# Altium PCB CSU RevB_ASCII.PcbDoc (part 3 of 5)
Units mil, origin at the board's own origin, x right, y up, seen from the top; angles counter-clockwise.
Board outline 5905.51 x 4330.71 mil, 8 copper layers (Top Layer, InternalPlane1, MidLayer1, InternalPlane2, MidLayer2, InternalPlane3, MidLayer3, Bottom Layer); 265 components, 387 nets, 1910 pads, 1151 vias.
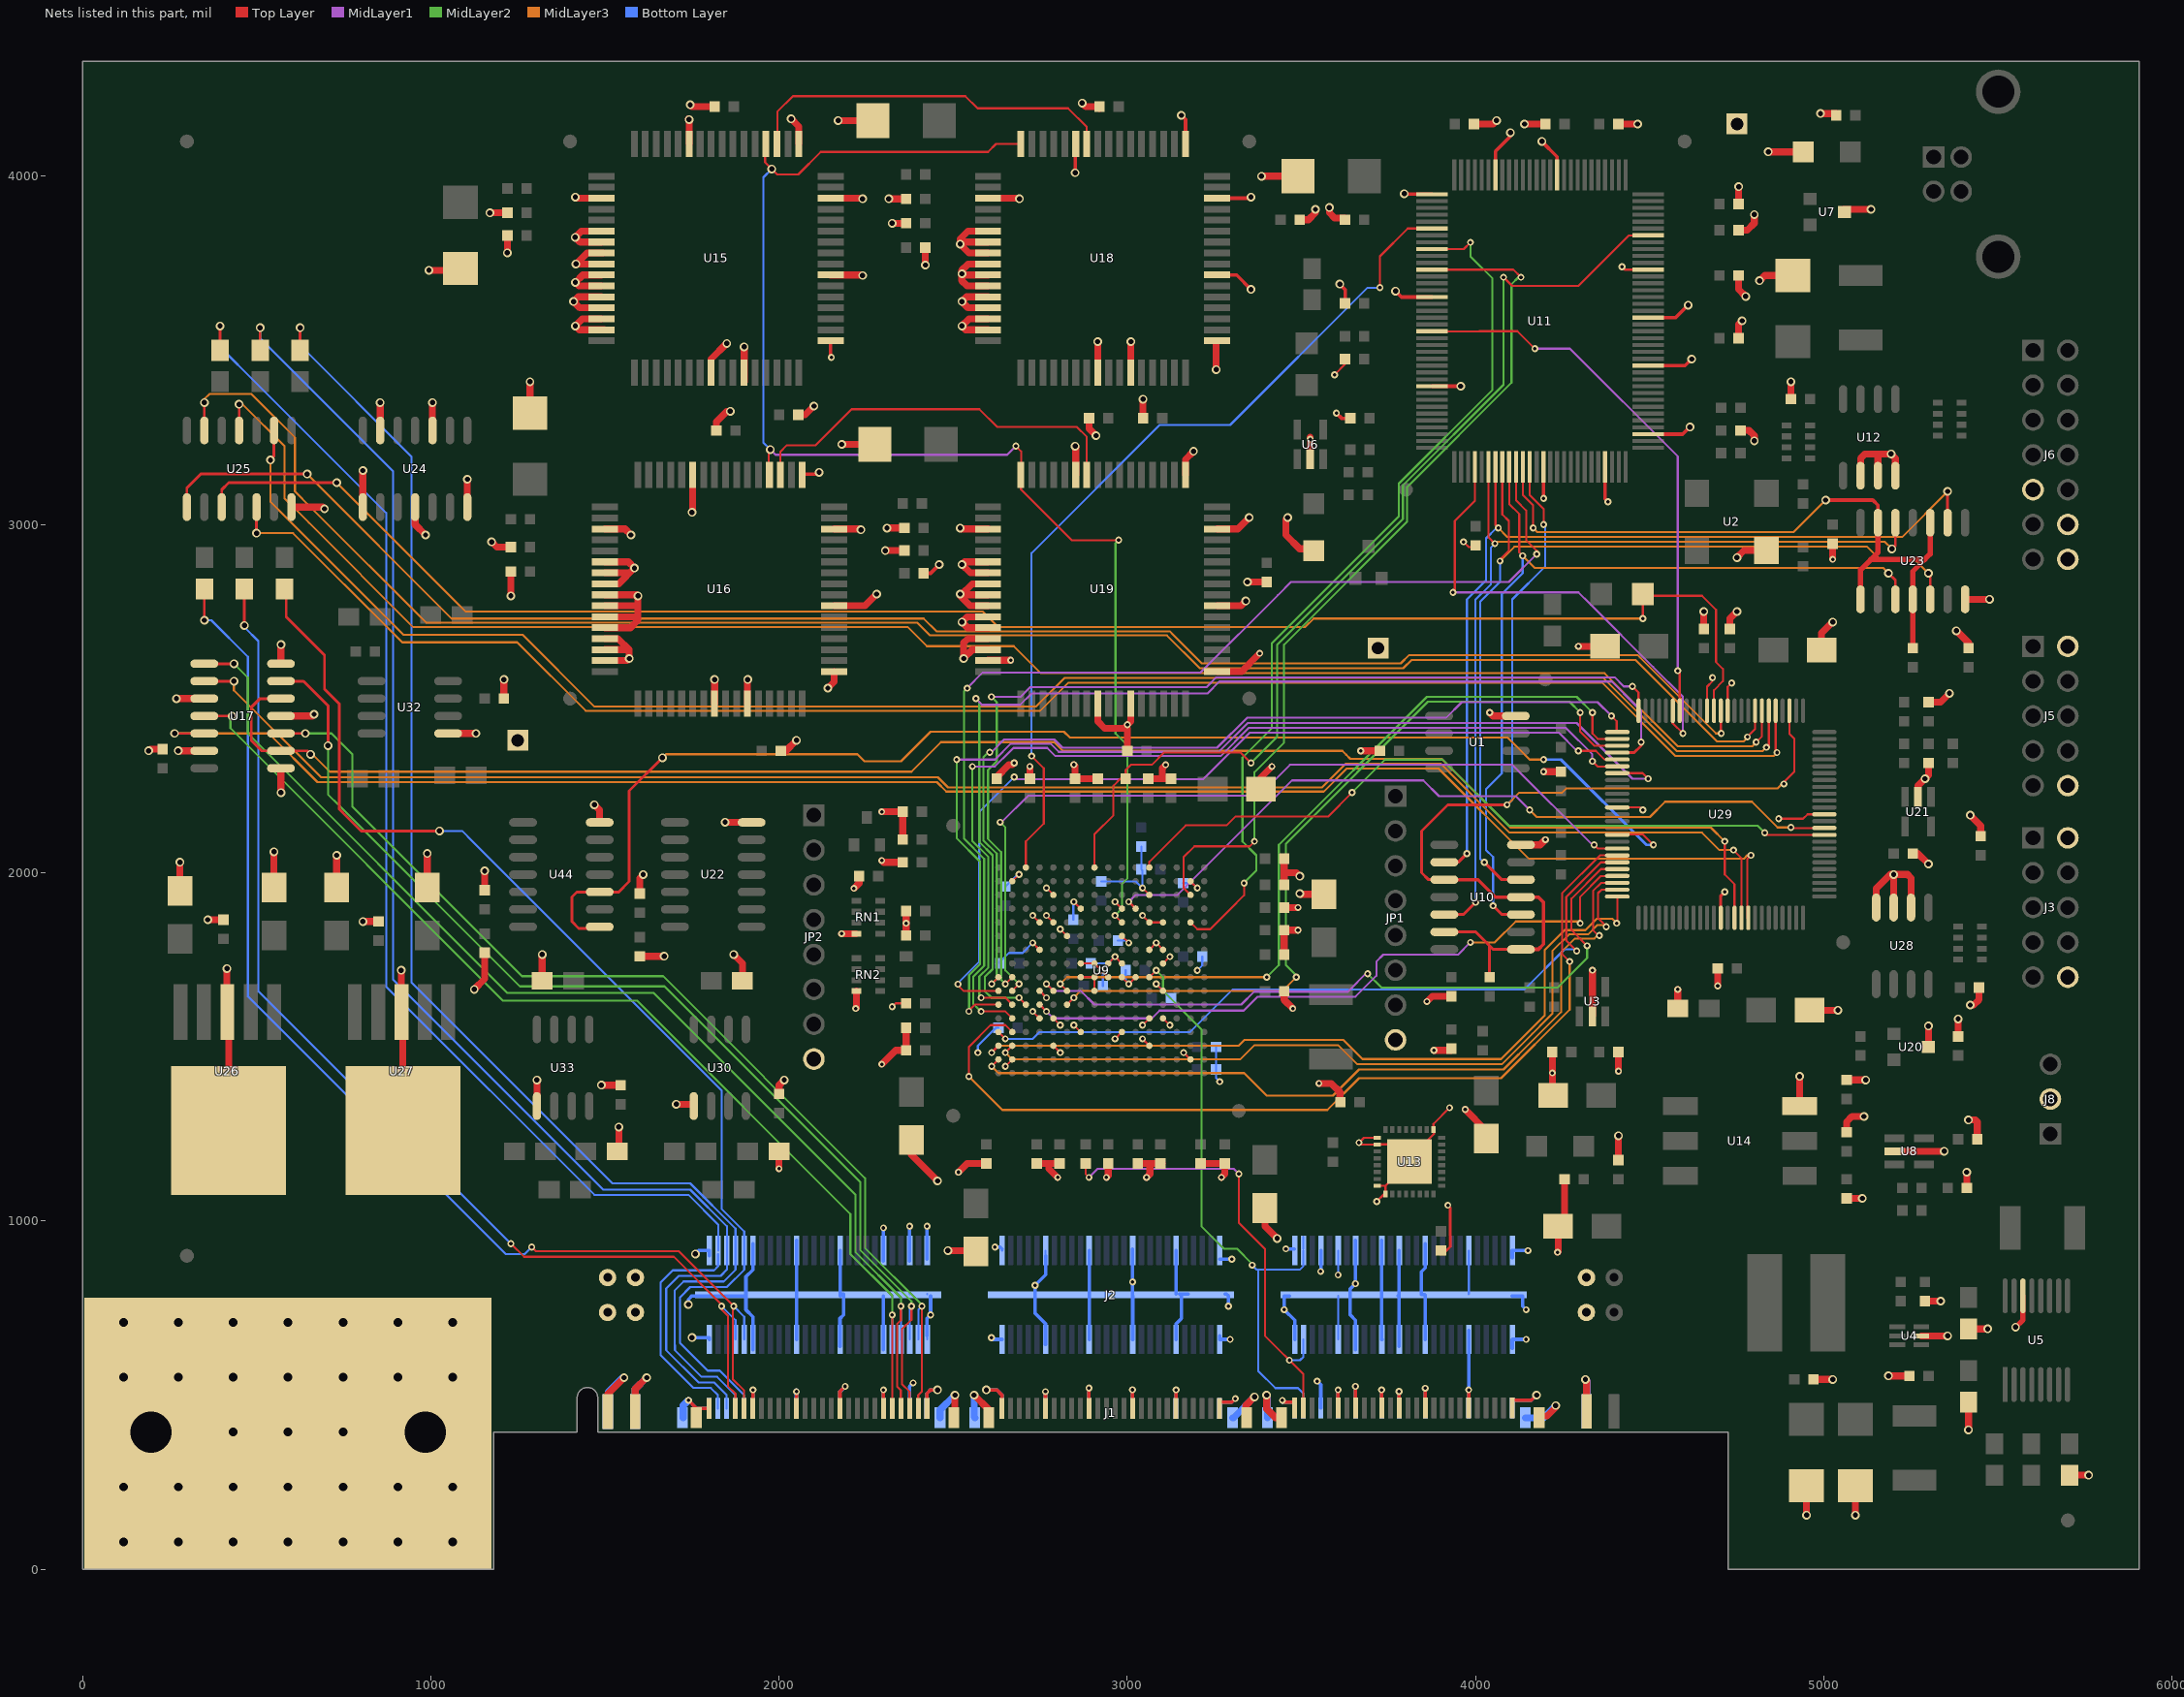
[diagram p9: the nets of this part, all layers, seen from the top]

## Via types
v1: diameter 20, hole 10, Top Layer to Bottom Layer, 647 vias
v2: diameter 25, hole 15, Top Layer to Bottom Layer, 352 vias
v3: diameter 20, hole 10, Top Layer to Bottom Layer, tented top, 151 vias
v4: diameter 20, hole 10, Top Layer to Bottom Layer, tented bottom, 1 vias

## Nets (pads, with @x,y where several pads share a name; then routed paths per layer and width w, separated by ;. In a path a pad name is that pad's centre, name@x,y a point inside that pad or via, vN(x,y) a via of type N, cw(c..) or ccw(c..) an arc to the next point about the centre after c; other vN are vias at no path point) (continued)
FIFO_TRANS_CLK: U9.E10 U15.52 U16.52 U18.64 U19.64 | length 4069.9
  Top Layer w6: U15.52@1962.44,4093 1960,4090.56 1960,4040 1995,4005 2055,4005 2120,4070 2600,4070 2623,4093 U18.64@2694.49,4093 ; U16.52@1972.44,3143 1970,3145.44 1970,3205 1975,3210 v2(1975,3215) ; v1(2680,3225) 2695,3210 2695,3143.51 U19.64@2694.49,3143 2694.49,3100.51 2840,2955 v1(2975,2955) ; v3(2964.65,1877.2) U9.E10@2984.33,1857.52
  MidLayer1 w6: v2(1975,3215) 1990,3200 2655,3200 v1(2680,3225)
  MidLayer2 w6: v3(2964.65,1877.2) 2984.33,1896.89 2984.33,1967.63 2999.7,1983 2999.7,2366.33 2966,2400.03 2966,2946 v1(2975,2955)
  Bottom Layer w6: v2(1975,3215) 1955,3235 1955,3996.98 v2(1979.01,4020.99)
FIRST_BYTE: U11.85 U29.19 | length 1587.4
  Top Layer w6: U11.85@3874.45,3554.65 4010,3554.65 ; 4010,3555 4120,3555 v1(4170,3505) ; v1(4580,2580) 4585.67,2574.33 U29.19@4585.67,2465
  MidLayer1 w6: v1(4170,3505) 4270.6,3505 4580,3195.6 v1(4580,2580)
FLAG_B: U9.A3 U11.70 | length 2542.4
  Top Layer w6: U9.A3@2708.74,2015 2708.74,2090 2760,2141.26 2760,2300 v1(2725,2335) ; v1(3725,3680) 3725,3770 3804.92,3849.92 U11.70@3890,3849.92
  Bottom Layer w6: v1(2725,2335) 2725,2917.91 3092.6,3285.51 3295,3285.51 3689.49,3680 v1(3725,3680)
FP_SEL_0_N: U9.D11 U29.86 | length 2259.9
  Top Layer w6: v3(3004.02,1916.57) U9.D11@3023.7,1896.89 ; v1@4906.61,2128.39 U29.86@5001.02,2128.39
  MidLayer1 w6: v3(3004.02,1916.57) 3023.7,1936.26 3144.14,1936.26 3472.88,2265 3850,2265 3895,2220 4115,2220 v1(4155,2180)
  MidLayer3 w6: v1(4155,2180) 4175,2160 4500,2160 4544,2204 4792.97,2204 4866.97,2130 v1(4905,2130)
FP_SEL_1_N: U9.A12 U29.85 | length 2165.6
  Top Layer w6: U9.A12@3063.07,2015 3063.07,2031.43 3167.64,2136 3284.94,2136 3309.94,2161 3576,2161 v1(3645,2230) ; v1(4830,2115) 4836.3,2108.7 U29.85@5001.02,2108.7
  MidLayer2 w6: v1(3645,2230) 3740,2325 3905,2325 4095,2135 4810,2135 v1(4830,2115)
FPGA_RESET_N: U9.M2 U11.112 | length 3145.1
  Top Layer w6: v1(2580,1601.61) 2649.68,1601.61 U9.M2@2669.37,1581.93 ; U11.112@4115.83,3165.63 4115.83,3069.17 4145,3040 4145,2955 4175,2925 v1(4175,2915)
  MidLayer1 w6: v1(2540,2530) 2585,2575 3210,2575 3431.86,2796.86 3470,2835 4095,2835 v1(4175,2915)
  MidLayer2 w6: v1(2540,2530) 2531.57,2521.57 2531.57,2097.45 2589,2040.03 2589,1732.94 2557.63,1701.57 2557.63,1623.99 v1(2580,1601.61)
FPGA_SEL_N: R21.1 U10.1 U10.4 U10.10 U10.13 U11.114 U29.3 | length 3372.7
  Top Layer w6: U11.114@4155.2,3165.63 4155.2,3085 4195,3045.2 v1(4195,3000) ; v1@4882.5,2257.5 4915,2290 4915,2384.8 4900.63,2399.17 U29.3@4900.63,2465
  Top Layer w8: U10.10@3900,1980 3865,1980 3845,2000 3845,2120 3920,2195 v1(4090,2195) ; U10.13@3910,1830 4000,1830 4050,1780 U10.1@4135,1780 ; R21.1@4039.99,1700 4039.99,1790.01
  Top Layer w10: U10.10@3900,1980 4007.14,1980 4057.14,1930 4180,1930 4195,1915 4195,1795 4180,1780 U10.1@4135,1780
  MidLayer3 w6: v1(4090,2195) 4125,2230 4248.03,2230 4260.03,2242 4867,2242 v1@4880,2255
  Bottom Layer w6: v1(4090,2195) 4105,2210 4105,2785 4200,2880 v1@4200,2995
  other v1: 4885,2255
FRAME_START: U9.E15 U11.73 | length 2562.9
  Top Layer w6: U9.E15@3181.18,1857.52 3200.87,1837.83 3237.83,1837.83 3292.93,1892.93 3335,1935 v1(3335,1970) ; U11.73@3865,3790 U11.73@3875,3790 ; U11.73@3874.45,3790.87 3965.87,3790.87 v1(3985,3810)
  MidLayer2 w6: v1(3335,1970) 3340,1970 3340,1976.4 3370,2006.4 3370,2050 3330.55,2089.45 3330.55,2330.55 3415,2415 3415,2659.4 3779.2,3023.6 3779.2,3117.23 4048.14,3386.17 4048.14,3706.86 3985,3770 v1(3985,3810)
GAIN_4X: J1.50 J2.50 U9.J12 | length 1735
  Top Layer w6: U9.J12@3063.07,1700.04 v3(3082.76,1719.72)
  MidLayer2 w6: v3(3082.76,1719.72) 3102.44,1700.04 3102.44,1660.67 3212.69,1550.42 3212.69,984.95 3264.02,933.62 3277.64,920 3315,920 3358.35,876.65 v1(3358.35,873.27)
  Bottom Layer w6: v1(3358.35,873.27) 3371.61,860 3495,860 3505.51,870.51 J2.50@3505.51,914.96 ; 3376,860 3376,569 3425.01,519.99 3490.01,519.99 3505,505 3505,463.05 J1.50@3505.21,462.85 ; J2.50@3505.51,920 J2.50@3505.51,954.49
GND: C1.2 C2.2 C3.1 C4.2 C5.1 C7.2 C8.1 C9.2 C10.2 C11.2 C12.2 C13.2 C14.2 C15.1 C16.2 C18.1 C19.2 C20.1 C21.2 C22.1 C23.2 C24.2 C25.1 C26.1 C27.1 C28.1 C29.2 C30.1 C31.2 C32.2 C33.1 C34.2 C35.1 C36.1 C37.1 C38.2 C39.2 C40.2 C41.2 C42.1 C43.1 C44.1 C45.1 C46.2 C47.1 C48.1 C49.2 C50.1 C51.1 C52.1 C53.1 C54.2 C55.2 C56.2 C57.1 C58.1 C59.1 C60.1 C61.1 C62.1 C63.1 C64.1 C65.1 C66.1 C67.1 C68.2 C69.2 C70.2 C71.2 C72.2 C73.1 C74.2 C75.1 C76.1 C77.2 C78.2 C79.2 C80.2 C81.2 C82.2 C83.2 C84.2 C85.2 C86.2 C87.2 C88.2 C89.2 C90.2 C91.2 C92.2 C93.2 C94.2 C95.2 C96.2 C97.2 C98.2 C99.2 C100.1 C101.2 C102.2 C103.2 C104.2 C105.1 C106.1 C107.2 C108.2 C109.2 C110.2 C111.2 C112.2 C113.1 C114.1 C115.1 C116.1 C117.1 C118.1 C119.1 C120.1 C121.1 C122.1 C123.1 C124.1 C125.1 C126.2 C127.2 C128.1 C129.1 C130.1 C131.1 C132.1 C133.1 C134.1 C135.1 C136.2 C137.2 C138.2 C140.1 C142.2 J1.1 J1.2 J1.11 J1.12 J1.21 J1.22 J1.27 J1.28 J1.31 J1.32 J1.37 J1.38 J1.41 J1.42 J1.46 J1.51 J1.52 J1.53 J1.54 J1.63 J1.64 J1.73 J1.74 J1.83 J1.84 J1.93 J1.94 J1.103 J1.104 J1.105 J1.106 J1.110 J1.115 J1.116 J1.125 J1.126 J1.135 J1.136 J1.145 J1.146 J1.155 J1.156 J1.157 J1.158 J1.159 J1.160 J1.161 J1.162 J1.163 J1.PC03 J1.PC04 J1.PC05 J1.PC06 J1.PC07 J1.PC08 J2.1 J2.2 J2.11 J2.12 J2.21 J2.22 J2.27 J2.28 J2.31 J2.32 J2.37 J2.38 J2.41 J2.42 J2.46 J2.51 J2.52 J2.53 J2.54 J2.63 J2.64 J2.73 J2.74 J2.83 J2.84 J2.93 J2.94 J2.103 J2.104 J2.105 J2.106 J2.110 J2.115 J2.116 J2.125 J2.126 J2.135 J2.136 J2.145 J2.146 J2.155 J2.156 J2.157 J2.158 J2.159 J2.PC03 J2.PC04 J2.PC05 J2.PC06 J2.PC07 J2.PC08 J3.2 J3.10 J5.2 J5.10 J6.9 J6.12 J6.14 J8.2 JP1.8 JP2.8 L2.2 pad.0 pad.1 pad.2 pad.3 pad.4 pad.5 R8.1 R9.1 R14.1 R15.1 R17.2 R20.1 R24.1 R39.1 R42.1 R48.1 R49.1 R51.2 R54.2 RN1.8 RN2.8 TP1.1 TP2.1 TP3.1 U1.4 U2.2 U3.2 U4.5 U5.14 U6.2 U7.3 U8.2 U9.B2 U9.B15 U9.C5 U9.C12 U9.D7 U9.D10 U9.E4 U9.E5 U9.E12 U9.E13 U9.F6 U9.F10 U9.G4 U9.G12 U9.G13 U9.H7 U9.H8 U9.H9 U9.H10 U9.H13 U9.J7 U9.J8 U9.J9 U9.J10 U9.J11 U9.K4 U9.K8 U9.K13 U9.M4 U9.M5 U9.M12 U9.M13 U9.N7 U9.N10 U9.P5 U9.P12 U9.R2 U9.R15 U10.7 U11.3 U11.13 U11.20 U11.27 U11.49 U11.58 U11.65 U11.80 U11.93 U11.116 U11.125 U12.2 U12.3 U12.4 U13.1 U13.2 U13.8 U13.9 U13.25 U13.T_PAD U14.3 U15.3 U15.6 U15.7 U15.8 U15.9 U15.10 U15.11 U15.12 U15.13 U15.14 U15.15 U15.24 U15.27 U15.33 U15.39 U15.46 U15.49 U15.59 U16.3 U16.6 U16.7 U16.8 U16.9 U16.10 U16.11 U16.12 U16.13 U16.14 U16.15 U16.24 U16.27 U16.33 U16.39 U16.46 U16.49 U16.59 U17.1 U17.4 U17.7 U17.10 U17.13 U18.3 U18.6 U18.7 U18.8 U18.9 U18.10 U18.11 U18.12 U18.13 U18.14 U18.15 U18.24 U18.27 U18.33 U18.39 U18.46 U18.49 U18.59 U19.3 U19.6 U19.7 U19.8 U19.9 U19.10 U19.11 U19.12 U19.13 U19.14 U19.15 U19.24 U19.27 U19.33 U19.39 U19.46 U19.49 U19.59 U20.3 U21.2 U22.7 U23.7 U24.1 U24.4 U24.7 U24.10 U24.13 U25.7 U26. U26.3 U27. U27.3 U28.2 U28.3 U28.4 U29.12 U29.15 U29.37 U29.63 U29.88 U30.5 U32.1 U33.5 U44.7 | length 33840.3
  Top Layer w6: v2(190,2350) v2@195,2355 ; v2(915,1720) v2@916,1719 ; v1@1924.71,514.71 v1(1925,515) ; C47.1@2045,3315.01 C47.1@2055,3315.02 ; v1@2049.71,509.71 v1(2050,510) ; v2@2110,3145 v2(2115,3150) ; v1@2148,3482 v1(2150,3480) ; v1(2220,1610) v1@2222,1612 ; v2@2232.99,2987.01 v2(2235,2985) ; v1@2299.71,514.71 v1(2300,515) ; v1(2325,1615) 2335.01,1625.01 C21.2@2365,1625.01 ; C103.2@2355,2175.01 C103.2@2365,2165.01 ; v2@2520,2795 v2@2523.03,2798.03 ; v2(2520,2990) v2@2522.99,2987.01 ; v3(2649.68,1444.13) U9.R2@2669.37,1463.82 ; U9.B2@2669.37,1975.63 v3(2689.06,1995.32) ; C83.2@2720.01,2260 C83.2@2720.01,2270 ; v3(2728.43,1601.61) U9.M4@2748.11,1581.93 ; v3(2728.43,1798.46) U9.G4@2748.11,1778.78 ; v3(2728.43,1877.2) U9.E4@2748.11,1857.52 ; C96.2@2734.99,1165 C96.2@2739.99,1165 ; U9.K4@2748.11,1660.67 v3(2767.8,1640.98) ; v1@2764.86,509.86 v1(2765,510) ; v3(2767.8,1877.2) U9.E5@2787.48,1857.52 ; v3(2767.8,1955.94) U9.C5@2787.48,1936.26 ; U9.P5@2787.48,1503.19 v3(2807.17,1483.5) ; U9.M5@2787.48,1581.93 v3(2807.17,1562.24) ; v3(2807.17,1837.83) U9.F6@2826.85,1818.15 ; v3(2846.54,1562.24) U9.N7@2866.22,1542.56 ; v3(2846.54,1916.57) U9.D7@2866.22,1896.89 ; U9.J7@2866.22,1700.04 U9.J8@2905.59,1700.04 ; U9.H7@2866.22,1739.41 U9.H8@2905.59,1739.41 U9.J9@2944.96,1700.04 ; v1(2889.86,519.86) v1@2890,519.73 ; U9.K8@2905.59,1660.67 U9.J8@2905.59,1700.04 ; v3(2925.28,1719.72) U9.J8@2905.59,1700.04 ; U9.H9@2944.96,1739.41 v3(2964.65,1759.09) U9.H10@2984.33,1739.41 ; v3(2964.65,1522.87) U9.N10@2984.33,1542.56 ; v3(2964.65,1916.57) U9.D10@2984.33,1896.89 ; U9.J10@2984.33,1700.04 v3(3004.02,1680.35) U9.J11@3023.7,1700.04 ; U9.F10@2984.33,1818.15 v3(3004.02,1798.46) ; 2990,2415 3000,2415 ; U19.27@3009.45,2485 U19.27@3009.45,2486 ; v3(3043.39,1522.87) U9.P12@3063.07,1503.19 ; v3(3043.39,1562.24) U9.M12@3063.07,1581.93 ; v3(3043.39,1877.2) U9.E12@3063.07,1857.52 U9.E13@3102.44,1857.52 ; v3(3043.39,1955.94) U9.C12@3063.07,1936.26 ; U9.G12@3063.07,1778.78 v3(3082.76,1798.46) U9.G13@3102.44,1778.78 ; v3(3082.76,1680.35) U9.K13@3102.44,1660.67 ; U9.M13@3102.44,1581.93 v3(3122.13,1562.24) ; U9.H13@3102.44,1739.41 v3(3122.13,1759.09) ; v3(3161.5,1483.5) U9.R15@3181.18,1463.82 ; U9.B15@3181.18,1975 v3@3200.87,1955.32 ; C91.2@3200,1165 C91.2@3209.99,1165 ; U19.46@3258,2987.01 U19.46@3265,2987.01 ; J1.53@3264.86,461.79 3264.86,479.86 J1.53@3265,480 ; C136.2@3383,2240 3383,2268 v1@3417.5,2302.5 ; v1(3595,3430) 3625,3460 R8.1@3625,3474.99 ; v1(3605,515) v1@3605.21,514.79 ; v1(3665,1225) 3678.9,1238.9 U13.1@3717.48,1238.9 ; v1@3670.79,1219.21 U13.2@3717.48,1219.21 ; v1@3715,1055 3737.48,1077.48 U13.9@3741.1,1077.48 3741.1,1101.1 ; U13.8@3717.48,1101.1 3741.1,1101.1 ; U13.2@3720,1220 3765,1220 U13.T_PAD@3775,1210 ; v1(3730,515) v1@3730.21,514.79 ; U13.T_PAD@3755,1115 3741.1,1101.1 ; v1(3780.21,510.21) v1@3785,515 ; v2(3795,3950) v2@3796.65,3948.35 ; U13.T_PAD@3855,1225 3880,1250 U13.25@3880,1265 ; U13.25@3878.9,1262.52 3878.9,1278.9 v1(3925,1325) ; v1(3965,2950) 3980,2935 C25.1@4000,2935 ; v1@4194.57,3075.43 v1(4195,3075) ; U29.37@4406.54,2187.44 4472.56,2187.44 v1(4480,2180) ; v1(4420,3740) 4428.19,3731.81 U11.27@4495,3731.81 ; U29.15@4664.41,2465 4664.41,2534.41 4680,2550 ; U29.12@4723.46,2465 4723.46,2533.46 v1(4735,2545) ; v1(4870,2155) 4940,2155 4952.76,2167.76 U29.88@5001.02,2167.76 ; 5152.5,3202.5 5155,3200 ; C10.2@5415,2640.01 C10.2@5415,2650
  Top Layer w8: C33.1@3900.01,915 3916,915 3927,926 3927,1038 v1(3920,1045) ; U29.63@4703.78,1870.51 4703.78,1933.78 v1(4715,1945)
  Top Layer w10: v1(1740,485) 1763.21,461.79 J1.155@1799.71,461.79 ; J1.145@1925,440 v1(1925,515) ; v1@2049.71,509.71 2050,509.41 J1.135@2050,440 ; U16.49@2070,3145 v2@2110,3145 ; v1@2148,3482 U15.33@2148,3527.56 ; J1.125@2175,445 2175,510 v1(2190,525) ; v1@2299.71,514.71 2300,514.41 J1.115@2300,440 ; C51.1@2415,2860.01 2435.01,2860.01 v2(2460,2885) ; J1.105@2424.71,461.79 2425,462.08 2425,505 2435,515 v2(2455,515) ; v2(2595,515) 2625,515 2639.86,500.14 J1.103@2639.86,461.79 ; v1@2764.86,509.86 2765,509.73 J1.93@2765,440 ; v2(2850,4010) U18.59@2850,4105 ; J1.83@2890,440 v1@2890,519.73 ; v1(3014.86,515.14) 3015,515 J1.73@3015,440 ; v1(3139.86,514.86) 3140,514.73 J1.63@3140,440 ; v2(3155,4175) 3166.93,4163.07 U18.49@3166.93,4093 ; U18.39@3258,3716.53 3313.47,3716.53 v2(3355,3675) ; U18.46@3258,3937.01 3352.01,3937.01 v2(3355,3940) ; J1.53@3264.86,479.86 3299.86,479.86 v1(3310,490) ; v1(3445,485) 3450,480 3475,480 3480.21,474.79 J1.51@3480.21,462.85 ; v1(3600,3320) 3615,3305 C22.1@3645,3305 ; J1.41@3605,445 3605,514.59 v1@3605.21,514.79 ; v2(3610,3690) 3625,3675 C20.1@3625,3634.99 ; J1.37@3655,445 v1(3655,525) ; J1.31@3730,445 3730,514.59 v1@3730.21,514.79 ; v2(3770,3670) 3786.93,3653.07 U11.80@3874.45,3653.07 ; J1.27@3780,445 3780,510 v1(3780.21,510.21) ; v2@3796.65,3948.35 U11.65@3874.45,3948.35 ; J1.21@3855,445 3855,519.59 v1(3855.21,519.79) ; U11.93@3874.45,3397.17 v2(3957.17,3397.17) ; J1.11@3980,445 3980,514.59 v1@3980.21,514.79 ; U11.58@4056.77,4003.72 4056.77,4071.77 4100,4115 v2(4100,4125) ; J1.1@4105.21,462.85 4105.21,484.79 4105,485 4160,485 v2(4175,500) ; v2(4190,4100) 4233.94,4056.06 U11.49@4233.94,4003.72 ; v1@4194.57,3075.43 U11.116@4194.57,3165.63 ; U11.125@4371.73,3165.63 4371.73,3073.27 v1(4380,3065) ; U11.3@4495,3259.37 4594.37,3259.37 v2(4615,3280) ; U11.13@4495,3456.22 4601.22,3456.22 v2(4620,3475) ; U11.20@4495,3594.02 4574.02,3594.02 v2(4610,3630)
  Top Layer w15: v2(5550,695) 5571.18,716.18 U5.14@5571.18,785
  Top Layer w20: v2@195,2355 C49.2@230.01,2355 ; v2(270,2500) U17.10@350,2500 ; v2(275,2350) U17.13@350,2350 ; C101.2@280,1950 v2(280,2030) ; v2(360,1865) C105.1@404.99,1865 ; v2(415,1725) 415,1605 420,1600 U26.@420,1260.28 ; C77.2@550,1955 v2(550,2060) ; v2(570,2230) U17.1@570,2300 ; U17.4@570,2450 660,2450 v2(665,2455) ; U17.7@570,2600 v2(570,2655) ; U25.7@600,3050 690,3050 v2(695,3045) ; C102.2@730,1955 v2(730,2050) ; v2(805,1860) C106.1@849.99,1860 ; U24.1@805,3050 v2(805,3155) ; U24.13@855,3270 v2(855,3350) ; U27.3@916,1600.29 v2@916,1719 ; U27.3@916,1610 920,1606 U27.@920,1260.28 ; U24.4@955,3055 955,3000 v2(985,2970) ; C78.2@990,1955 v2(990,2055) ; v2(995,3730) C40.2@1080,3730 ; U24.10@1005,3270 v2(1005,3350) ; U32.1@1055,2400 v2(1130,2400) ; U24.7@1105,3055 v2(1105,3130) ; v2(1125,1665) 1155,1695 C63.1@1155.01,1770 ; C71.2@1155.01,1950 v2@1155.01,2004.99 ; v2@1170.01,3894.99 C42.1@1220,3894.99 ; v2(1175,2950) 1190.01,2934.99 C43.1@1230,2934.99 ; C140.1@1210,2500.01 v2(1210,2555) ; v2(1220,3780) C44.1@1220,3829.99 ; v2(1230,2795) C45.1@1230,2864.99 ; v2(1285,3410) 1285,3335 1295,3325 C41.2@1300,3325 ; U33.5@1305,1330 v2(1305,1405) ; R49.1@1320,1690 v2(1320,1765) ; v2(1415,3940) 1417.99,3937.01 U15.3@1490,3937.01 ; v2(1470,2195) 1484.96,2180.04 U44.7@1484.96,2144.57 ; v2(1490,1390) C142.2@1545.01,1390 ; U15.14@1490,3590.55 1435.55,3590.55 v2(1415,3570) 1425.94,3559.06 U15.15@1499.06,3559.06 ; U15.13@1490,3622.05 1427.95,3622.05 v2(1410,3640) 1423.54,3653.54 U15.12@1490,3653.54 ; U15.11@1490,3685.04 1424.96,3685.04 v2(1415,3695) 1436.53,3716.53 U15.10@1490,3716.53 ; U15.9@1490,3748.03 v2(1416.97,3748.03) 1448.94,3780 U15.8@1495,3780 ; U15.7@1490,3811.02 1428.61,3811.02 v2(1414.82,3824.82) 1432.52,3842.52 U15.6@1490,3842.52 ; U16.15@1500,2609.06 1564.06,2609.06 v2(1570,2615) 1570,2638.63 1568.08,2640.55 U16.14@1500,2640.55 ; U16.13@1500,2672.05 1537.95,2672.05 1568.76,2641.24 ; U16.12@1500,2703.54 1573.54,2703.54 1595,2725 ; U16.11@1500,2735.04 1584.96,2735.04 1595,2725 ; U16.10@1500,2766.53 1591.53,2766.53 1595,2770 ; U16.9@1500,2798.03 1591.97,2798.03 v2(1595,2795) 1595,2725 ; U16.8@1500,2829.53 1539.53,2829.53 v2(1585,2875) 1567.48,2892.52 U16.6@1500,2892.52 ; U16.7@1500,2861.02 1571.02,2861.02 ; U16.3@1500,2987.01 1557.99,2987.01 v2(1575,2970) ; J1.PC07@1508.31,452.85 1508.31,503.31 v2(1555,550) ; R51.2@1540,1200 v2(1540,1270) ; J1.PC05@1590,455.64 J1.PC05@1587.21,452.85 1587.21,517.21 v2(1620,550) ; C76.1@1600.01,1760 v2(1670,1760) ; C75.1@1599.99,1940 1599.99,1984.99 v2(1610,1995) ; v2(1705,1335) U30.5@1755,1335 ; v2@1740,4165 v2(1741.97,4163.03) U15.59@1741.97,4093 ; v2(1745,4205) 1750,4200 C52.1@1815,4200 ; v2(1750,3035) 1751.97,3036.97 U16.59@1751.97,3143 ; U15.24@1805,3420 1805,3475 v2(1850,3520) ; U16.24@1814.96,2486 1814.96,2554.96 v2(1815,2555) ; C53.1@1820,3269.99 1820,3295 1850,3325 v2(1860,3325) ; v2(1845,2145) 1845.43,2144.57 U22.7@1921.14,2144.57 ; v2(1870,1765) 1895,1740 R48.1@1895,1690 ; U15.27@1900,3410 v2(1900,3510) ; U16.27@1909.45,2486 1909.45,2554.45 v2(1910,2555) ; v1(2000,1150) R54.2@2000,1200 ; C137.2@2000.01,1365 2000.01,1390.01 v2(2015,1405) ; C48.1@2005,2350.01 2020.01,2350.01 v2(2050,2380) ; v2(2035,4165) 2056.93,4143.07 U15.49@2056.93,4093 ; C47.1@2055,3315.02 2075.02,3315.02 v2(2100,3340) ; v2(2140,2530) 2158,2548 U16.33@2158,2577.56 ; U15.39@2148,3716.53 2238.47,3716.53 v2(2240,3715) ; U15.46@2148,3937.01 v2@2237.99,3937.01 ; U16.39@2158,2766.53 2246.53,2766.53 v2(2280,2800) ; U16.46@2158,2987.01 v2@2232.99,2987.01 ; v2(2170,4160) C55.2@2270,4160 ; v1(2180,1825) RN1.8@2220,1825 ; v2(2180,3230) C56.2@2270,3230 ; v1(2215,1955) 2230,1970 C46.2@2230,1990.01 ; v1@2222,1612 RN2.8@2222,1660 ; v1(2295,1450) 2335.01,1490.01 C99.2@2365,1490.01 C132.1@2365,1554.99 ; v1(2295,2035) 2299.99,2030.01 C98.2@2355,2030.01 ; v1(2295,2175) C103.2@2355,2175.01 C54.2@2355,2095.01 ; v2@2305.01,2924.99 C58.1@2360,2924.99 ; v2@2310.01,2989.99 C60.1@2360,2989.99 ; v2@2315.01,3934.99 C59.1@2365,3934.99 ; v2@2325.01,3864.99 C57.1@2365,3864.99 ; C14.2@2365,1820.01 C134.1@2365,1884.99 ; C126.2@2380,1230 2380,1190 v2(2455,1115) ; v2(2420,3745) C50.1@2420,3795.01 ; v2(2485,915) C109.2@2565,915 ; J1.158@2502.21,434.79 2505,437.58 v2(2505,500) ; v1(2515,1140) 2540,1165 C97.2@2594.99,1165 ; v2@2520,2795 2548.47,2766.53 U19.10@2600,2766.53 ; v2@2522.99,2987.01 U19.3@2600,2987.01 ; v2(2525,3720) 2528.47,3716.53 U18.10@2600,3716.53 ; v2(2560,500) 2600,460 J1.159@2600,435 ; U19.15@2600,2610 v1(2665,2610) ; U19.14@2600,2640.55 2555.55,2640.55 v2(2530,2615) 2530,2660 2542.05,2672.05 U19.13@2600,2672.05 ; U19.12@2600,2703.54 2541.46,2703.54 v2(2525,2720) 2540.04,2735.04 U19.11@2600,2735.04 ; U19.9@2600,2798.03 2523.03,2798.03 2554.53,2829.53 U19.8@2605,2829.53 ; U19.7@2600,2861.02 2548.98,2861.02 v2(2525,2885) 2532.52,2892.52 U19.6@2600,2892.52 ; U18.15@2600,3559.06 2535.94,3559.06 v2(2525,3570) 2545.55,3590.55 U18.14@2600,3590.55 ; U18.13@2600,3622.05 2542.95,3622.05 v2(2525,3640) 2538.54,3653.54 U18.12@2600,3653.54 ; U18.11@2600,3685.04 2599.96,3685 2540,3685 2525,3700 2525,3730 2543.03,3748.03 U18.9@2600,3748.03 ; U18.8@2600,3779.53 2599.53,3780 2545,3780 v2(2520,3805) ; U18.7@2600,3811.02 2526.02,3811.02 v2(2520,3805) ; U18.6@2600,3842.52 2542.52,3842.52 2520,3820 v2(2520,3805) ; U18.3@2600,3937.01 2687.99,3937.01 v2(2690,3935) ; C82.2@2625.01,2270 2625.01,2275.01 2660,2310 2670,2310 v1(2675,2315) ; C83.2@2720.01,2270 v1@2720.01,2304.99 ; C96.2@2739.99,1165 C95.2@2804.99,1165 ; 2775,1165 2775,1150 v1(2800,1125) ; v1(2846.54,2310.28) 2850.01,2306.8 C81.2@2850.01,2270 C84.2@2915.01,2270 ; v2(2850,3225) 2851.97,3223.03 U19.59@2851.97,3143 ; v2(2870,4210) 2880.01,4199.99 C61.1@2920,4199.99 C61.1@2920,4195 ; C67.1@2890,3310 2890,3275 v2(2910,3255) ; U19.24@2914.96,2486 2914.96,2435.04 2935,2415 2990,2415 3009.45,2434.45 U19.27@3009.45,2486 ; U18.24@2915,3440 v2(2915,3525) ; v1(2940,1125) 2945.01,1130.01 R20.1@2945.01,1165 ; C62.1@3000,2349.99 3000,2415 ; U18.27@3010,3440 v2(3010,3525) ; C94.2@3029.99,1165 C93.2@3099.99,1165 ; C66.1@3045,3305 v2(3045,3360) ; v1(3055,1125) 3065,1135 3065,1165 ; C86.2@3060.01,2270 C85.2@3125.01,2270 ; 3100,2270 3100,2300 v1(3110,2310) ; U19.49@3166.93,3143 3166.93,3186.93 v2(3190,3210) ; C91.2@3209.99,1165 C92.2@3279.99,1165 3279.99,1135.01 v1(3270,1125) ; v2(3255,3445) U18.33@3255,3527.56 ; U19.33@3258,2577.56 3327.56,2577.56 v1(3380,2630) ; U19.39@3258,2766.53 3326.53,2766.53 v2(3340,2780) ; U19.46@3258,2987.01 3317.01,2987.01 v2(3350,3020) ; J1.163@3340,435 3340,470 v2(3365,495) ; v2(3345,2835) C65.1@3400.01,2835 ; C136.2@3383,2240 3383,2273 v1(3415,2305) ; v2(3385,4000) 3385.22,4000.22 3460,4000.22 3474.78,4015 C32.2@3490,4015 ; C111.2@3395,1045 3395,985 v2(3430,950) ; v2(3400,500) 3400,460 3425,435 J1.161@3440,435 ; C130.1@3450,1660.01 3450,1635 v1(3475,1610) ; C90.2@3450,1765 C128.1@3450,1835.01 v1(3490,1835) ; C89.2@3450,1899.99 v1@3489.99,1899.99 ; C88.2@3450,1965 C87.2@3450,2039.99 ; 3450,2000 3485,2000 v2(3495,1990) ; v2(3460,3020) 3455,3015 3455,2970 3495,2930 C2.2@3535,2930 ; v2(3495,1940) 3497,1938 C127.2@3565,1938 3577,1950 C127.2@3580,1950 ; C64.1@3495,3875.01 3520.01,3875.01 3540,3895 v2(3540,3905) ; U6.2@3525,3187.68 v1@3525,3250 ; v1(3550,1395) 3585,1395 3610,1370 C36.1@3610,1340 ; v2(3580,3910) 3580,3895 3595,3880 C18.1@3625,3880 ; v1(3670,2350) C11.2@3725,2350.01 ; v1(3860,1630) 3875,1645 C23.2@3929.99,1645 ; v1(3880,1490) R42.1@3930.01,1490 ; v1(3970,1320) 4030,1260 C29.2@4030,1235 ; C15.1@3995,4150.01 4049.99,4150.01 v2(4060,4160) ; v1(4040,2460) 4050,2450 U1.4@4115,2450 ; U10.7@4130,2080 4185,2080 v1(4200,2095) ; v2@4140.01,4149.99 C30.1@4200,4149.99 ; J1.162@4182.21,434.79 4187.42,440 4205,440 4230,465 v2(4230,470) ; v1(4195,2290) C79.2@4245.01,2290 ; C1.2@4220,1355 C8.1@4220,1484.99 ; v1(4235,910) 4237,912 C31.2@4237,985 4255,1003 C35.1@4255,1119.99 ; v1(4295,2650) C70.2@4372,2650 ; v2(4315,545) 4318.31,541.69 J1.PC03@4318.31,453.35 ; U3.2@4335,1590 v1(4335,1720) ; C38.2@4410.01,1175 v2(4410,1245) ; v1(4410,1430) C3.1@4410,1485.01 ; C28.1@4410,4150.01 v2(4465,4150) ; C110.2@4580,1605 v1(4580,1665) ; C73.1@4654.99,2700 v2(4655,2750) ; v1(4695,1675) C113.1@4695,1724.99 ; C72.2@4730.01,2700 4730.01,2730.01 v2(4750,2750) ; v2(4750,2905) 4770,2925 U2.2@4834.94,2925 4840,2930.06 U2.2@4840,2935 ; R17.2@4750,3850 R17.2@4755,3850 ; C9.2@4755,3534.99 4755,3575 v2(4765,3585) ; C27.1@4755,3720 4755,3675 v2(4775,3655) ; R17.2@4755,3844.99 4779.99,3844.99 4800,3865 v2(4800,3890) ; R9.1@4755,3920.01 v2(4755,3970) ; C26.1@4760,3270.01 4784.99,3270.01 4800,3255 v2(4800,3240) ; v2(4815,3700) 4830,3715 C13.2@4910,3715 ; v2(4840,4070) L2.2@4940,4070 ; C39.2@4905,3360.01 v2(4905,3410) ; U14.3@4930,1330 v2(4930,1415) ; C104.2@4949.78,234.78 C104.2@4950,235 ; v2@4950,160.37 C104.2@4950,245 ; C112.2@4958,1605 v2(5040,1605) ; C100.1@4970,545.01 v2(5025,545) ; C69.2@4980,2640 C69.2@4993,2640 4993,2688 v2(5025,2720) ; v2(4990,4180) C5.1@5035,4180 ; v1(5025,2900) C68.2@5024.99,2945 ; U7.3@5055,3905 v2(5135,3905) ; U7.3@5058.43,3897.6 U7.3@5065.83,3905 ; C37.1@5065.01,1065 v2(5110,1065) ; C34.2@5065.01,1255 5065.01,1285.01 5080,1300 v2(5115,1300) ; R24.1@5064.99,1405 v2(5120,1405) ; C107.2@5089.78,240.15 5089.78,155.22 v2(5090,155) ; U12.2@5105,3135 5105,3190 5117.5,3202.5 v2(5192.5,3202.5) 5205,3190 U12.4@5205,3140 ; U28.4@5150,1900 5150,1955 5190,1995 5240,1995 5250,1985 U28.2@5250,1900 ; U12.3@5155,3140 5155,3200 ; v2(5185,555) C7.2@5245,555.01 ; U28.3@5200,1900 v2(5200,1995) ; U8.2@5205,1200 v2(5345,1200) ; C80.2@5255,2054.99 5270.01,2054.99 v2(5300,2025) ; U21.2@5270,2217.32 5270,2250 5300,2280 C74.2@5299.99,2315 ; U4.5@5279.45,670 v2(5355,670) ; R15.1@5290.01,770 v2(5335,770) ; U20.3@5300,1500 v2(5300,1560) ; R39.1@5299.99,2490 5335,2490 v2(5360,2515) ; v2(5380,2695) 5415,2660 C10.2@5415,2650 ; C138.2@5385.01,1530 v2@5385.01,1579.99 ; U23.7@5405,2785 v2(5475,2785) ; R14.1@5410,1090 v2(5410,1140) ; v2(5415,400) C19.2@5415,480 ; C4.2@5415,690 v2(5470,690) ; v2(5415,1290) 5435,1290 5440,1285 C24.2@5440,1234.99 ; v2(5420,1620) 5430,1620 5445,1635 C108.2@5445,1669.99 ; v2(5420,2165) 5450.01,2134.99 C12.2@5450.01,2105 ; C16.2@5705,270 v2(5760,270)
  Bottom Layer w6: J1.156@1800,455 J1.156@1800.2,455.2 ; J1.146@1924.71,461.79 J1.146@1925,462.08 ; v1@2049.71,514.71 v1@2050,515 ; J2.159@2050.2,789.8 2050,790 2050.2,790.2 J2.136@2050.2,914.96 ; v1@2189.71,525 v1(2190,525) ; v1@2299.71,514.71 v1(2300,515) ; J2.159@2300,785 J2.159@2300.2,785.2 ; v1(2300,980) v1@2300.2,979.8 ; J2.115@2300.2,640 J2.115@2300.2,670 ; J2.159@2375,790 J2.159@2375.2,790.2 ; v1(2375,985) v1@2375.2,984.8 ; J2.159@2425,790 J2.159@2425.2,790.2 ; v1(2425,985) v1@2425.2,984.8 ; J2.105@2425.2,659.84 J2.105@2425.2,670 ; v1(2570.94,1483.5) 2570.94,1503.19 2622.76,1555.01 C121.1@2630,1555.01 ; C115.1@2635,1740.01 2635,1744.41 2660.18,1769.59 2699.55,1769.59 v3(2728.43,1798.46) ; J2.104@2640.35,914.96 J2.104@2640.35,919.65 ; C133.1@2650.01,1960 2685.32,1995.32 v3(2689.06,1995.32) ; v1@2764.86,509.86 v1(2765,510) ; J2.94@2765.35,900 J2.94@2765.35,914.96 ; C123.1@2845.01,1865 2845.01,1915.05 v3(2846.54,1916.57) ; J2.158@2890,785 J2.158@2890.35,785.35 ; C116.1@2895,1739.99 2945.54,1739.99 v3(2964.65,1759.09) ; C124.1@2925.01,1975 3024.33,1975 v3(3043.39,1955.94) 3043.39,2006.62 C135.1@3040,2010.01 C117.1@3039.99,2075 ; v3(2925.28,1719.72) 2930,1715 C125.1@2930,1674.99 ; C129.1@2973,1804.99 2997.49,1804.99 v3(3004.02,1798.46) ; C114.1@2995,1720.01 2995,1689.37 v3(3004.02,1680.35) ; v1@3010,520 v1(3014.86,515.14) ; J2.158@3015,785 J2.158@3015.35,784.65 ; v3(3082.76,1680.35) 3123.12,1639.99 C119.1@3125,1639.99 ; v1(3139.86,514.86) v1@3140,515 ; C131.1@3160.01,1970 3186.81,1970 v3(3200.87,1955.94) ; v3(3200.87,1719.72) 3215,1733.86 C118.1@3215,1759.09 ; C120.1@3255,1499.99 3255,1410 v1(3265,1400) ; J1.54@3264.86,461.79 3264.86,479.86 J1.54@3265,480 ; v1@3294.84,659.84 v1(3295,660) ; v1(3555,855) v1@3555.51,855.51 ; J1.42@3605,463.05 J1.42@3605.21,462.85 ; J2.157@3605,785 3605.51,784.49 J2.41@3605.51,659.84 ; v1(3605,845) 3605.51,845.51 J2.42@3605.51,914.96 ; v1(3655,525) v1@3655.21,524.79 ; v1(3730,515) v1@3730.21,514.79 ; J2.157@3730,785 3730.51,785.51 J2.32@3730.51,914.96 ; J1.28@3780,463.05 J1.28@3780.21,462.85 ; J2.27@3780.51,659.84 3780.51,779.49 3775,785 J2.157@3780.51,790.51 ; J1.22@3855,463.05 J1.22@3855.21,462.85 ; J2.157@3980,790 3980.51,790.51 J2.12@3980.51,914.96 ; v1@4144.84,659.84 v1(4145,660) ; v1@4149.96,914.96 v1(4150,915)
  Bottom Layer w10: v1(1740,485) 1763.21,461.79 J1.156@1799.71,461.79 ; v2(1740,760) 1740,775 1750,785 J2.159@1905,785 ; v2(1750,665) J2.155@1800,665 ; v2(1760,905) 1769.96,914.96 J2.156@1800.2,914.96 1800,914.76 J2.156@1800,900 ; J2.155@1800,659.84 J2.155@1800.2,659.84 ; J1.146@1925,462.08 v1(1925,515) ; J2.145@1925,630 1925,725 1905,745 1905,839.8 1925.2,860 1925.2,934.8 J2.146@1925,935 ; J1.136@2049.71,461.79 v1@2049.71,514.71 ; J2.136@2050,945 2050,660.04 J2.135@2050.2,659.84 ; J1.126@2174.71,461.79 2174.71,509.71 v1(2190,525) ; J2.125@2175,640 2175,720 2185,730 2185,790 2180,790 2175.2,785.2 J2.126@2175.2,914.96 ; J1.116@2299.71,461.79 v1@2299.71,514.71 ; J2.115@2300,630 J2.159@2300,785 ; J2.116@2300,885 2300,979.61 v1@2300.2,979.8 ; J1.110@2374.71,461.79 2374.71,524.71 v1(2385,535) ; J2.110@2375,885 2375,984.61 v1@2375.2,984.8 ; J1.106@2424.71,461.79 2424.71,504.71 2435,515 v2(2455,515) ; J2.106@2425,890 2425,984.61 v1@2425.2,984.8 ; J2.105@2425.2,670 2425.2,720.2 v1(2435,730) J2.159@2435,785 ; v2(2595,515) 2625,515 2640,500 2640,461.93 J1.104@2639.86,461.79 ; v1(2610,665) 2615.16,659.84 J2.103@2640.35,659.84 ; v1(2620,925) 2635,925 J2.104@2640.35,919.65 ; J1.94@2764.86,461.79 v1@2764.86,509.86 ; J2.93@2765,645 2765,705 2735,735 v1(2735,815) 2765.35,845.35 J2.94@2765.35,900 ; J1.84@2889.86,461.79 v1(2889.86,519.86) ; J2.83@2890.35,659.84 J2.84@2890.35,914.96 ; J1.74@3014.86,461.79 v1(3014.86,515.14) ; J2.158@3015,785 J2.74@3015,920 ; J2.73@3015.35,659.84 J2.158@3015.35,784.65 ; J1.64@3139.86,461.79 v1(3139.86,514.86) ; J2.158@3140,790 J2.64@3140,914.96 ; J2.63@3140.35,659.84 3140.35,705.35 3155,720 3155,785 3150,790 J2.158@3175,790 ; J1.54@3265,480 3300,480 v1(3310,490) ; J2.53@3265,670 3265,660.2 J2.53@3265.35,659.84 v1@3294.84,659.84 ; J2.54@3265,890 v1@3299.61,890 ; J2.158@3280,790 3285,790 3290,785 v1(3290,755) ; v1@3445,480 J1.52@3480,480 ; v1(3455,920) J2.52@3480,920 ; J2.157@3465,785 3450,785 v1(3450,745) 3480.51,714.49 J2.51@3480.51,659.84 ; v1(3545,540) 3555.21,529.79 J1.46@3555.21,462.85 ; v1@3555.51,855.51 J2.46@3555.51,914.96 ; J1.42@3605,463.05 v1(3605,515) ; J2.37@3655,630 3655,715 3640,730 3640,805 v1(3655,820) J2.38@3655,945 ; J1.38@3655.21,462.85 v1@3655.21,524.79 ; J2.32@3730,945 3730,660.35 J2.31@3730.51,659.84 ; J1.32@3730.21,462.85 v1@3730.21,514.79 ; J1.28@3780,463.05 v1@3780,505 ; J2.27@3780,640 3780,914.45 J2.28@3780.51,914.96 ; J1.22@3855,463.05 v1@3855,520 ; J2.22@3855,935 3855,865 3844,854 3844,789 3853.91,789 3855.51,787.4 J2.21@3855.51,659.84 ; J1.12@3980,450 J2.11@3980,685 ; J2.1@4105,635 4105,659.33 J2.1@4105.51,659.84 v1@4144.84,659.84 ; J2.157@4105,785 4135,785 4135,755 v1(4145,745) ; J2.2@4105,895 4105,914.45 J2.2@4105.51,914.96 v1@4149.96,914.96 ; J1.2@4105.21,462.85 4105.21,484.79 4105,485 4160,485 v2(4175,500)
  Bottom Layer w20: J1.PC08@1508.31,452.85 1510,454.54 1510,510 1550,550 v2(1555,550) ; J1.PC06@1587.21,452.85 1587.21,517.21 v2(1620,550) ; J1.157@1725,435 1725,470 v1(1740,485) ; J1.158@2462.21,434.79 2462.21,457.21 v2(2505,500) ; v2(2560,500) 2560,437 J1.159@2562.21,434.79 ; J1.160@3302.21,434.79 3304.79,434.79 v2(3365,495) ; v2(3400,500) 3402.21,497.79 J1.161@3402.21,434.79 ; J1.162@4142.21,434.79 4194.79,434.79 v2(4230,470) ; v2(4315,545) 4320,540 4320,455.04 J1.PC04@4318.31,453.35
  other v1: 3980,515 3015,825 3300,890 3715.75,1055.75 4220,1425 2365,1855 3490,1900 2720,2305 3000,2425 4680,2560 3525,3245
  other v2: 4950,155 5385,1580 1155,2005 5290,2270 2520,2800 2305,2925 2310,2990 2325,3865 1170,3895 2240,3935 2315,3935 4140,4150
GPS_1HZ: J1.49 J2.49 R19.1 | length 1334
  Top Layer w6: R19.1@2880.02,1165 2880.01,1134.99 v1(2890,1125) ; v1(3320,1135) 3320,995 3395,920 3395,670 3505,560 J1.49@3505,462.85
  MidLayer1 w6: v1(2890,1125) 2915,1150 3305,1150 v1(3320,1135)
  Bottom Layer w6: v1(3465,600) 3495.51,600 3505.51,610 J2.49@3505.51,659.84
I_ADDR0_A: J1.107 J2.107 U17.3 | length 3126.2
  Top Layer w6: J1.107@2399.71,461.79 2399.71,499.71 2410,510 v1(2410,755)
  Top Layer w8: U17.3@570,2400 v2(640,2400)
  MidLayer2 w6: v2(640,2400) 715,2400 775,2340 775,2190 1262.29,1702.71 1667.29,1702.71 2247,1123 2247,922.4 2410,759.4 v1(2410,755)
  Bottom Layer w6: J2.107@2400.2,659.84 2400,660.04 2400,745 v1(2410,755)
I_ADDR0_B: J1.109 J2.109 U17.6 | length 3241.7
  Top Layer w6: J1.109@2374.71,461.79 2374.71,510 2352.71,532 2352.71,689 2380,716.29 v1(2380,755)
  Top Layer w8: U17.6@565,2550 635,2550 705,2480 v2(705,2365)
  MidLayer2 w6: v2(705,2365) 705,2225 736.53,2193.47 1256.2,1673.8 1671.2,1673.8 2233,1112 2233,916.6 2380,769.6 v1(2380,755)
  Bottom Layer w6: J2.109@2375.2,659.84 2375.2,750.2 v1(2380,755)
I_ADDR1: J1.111 J2.111 U17.8 | length 3361.5
  Top Layer w6: J1.111@2349.71,461.79 2349.71,514 2338.71,525 2338.71,704 2349.71,715 v1@2349.71,754.71
  Top Layer w8: U17.8@355,2600 v2(435,2600)
  MidLayer2 w6: v2(435,2600) 475,2560 475,2400 1220,1655 1640,1655 2219,1076 2219,910.8 2350,779.8 v1(2350,755)
  Bottom Layer w6: v1(2350,755) 2350,660.04 J2.111@2350.2,659.84
I_ADDR2: J1.113 J2.113 U17.11 | length 3153.2
  Top Layer w6: J1.113@2324.71,461.79 2324.71,729.71 v1(2325,730)
  Top Layer w8: U17.11@350,2450 v2(430,2450)
  MidLayer2 w6: v2(430,2450) 425,2445 425,2415 1207.18,1632.82 1592.18,1632.82 2205,1020 2205,905 2325,785 v1(2325,730)
  Bottom Layer w6: v1(2325,730) 2325.2,729.8 J2.113@2325.2,659.84
IFCLK: R43.2 U9.A8 U11.32 | length 2899.8
  Top Layer w6: U9.A8@2905.59,2015 2905.59,2110.59 2960,2165 2960,2250 2980,2270 R43.2@2995.01,2270 2995.01,2295.01 3010,2310 3070,2310 3105,2345 3325,2345 v1(3355,2315) ; v1(4080,3710) 4105,3685 4295,3685 4326.03,3716.03 4440.24,3830.24 U11.32@4495,3830.24
  MidLayer2 w6: v1(3355,2315) 3430,2390 3430,2654.6 3791.2,3015.8 3791.2,3112.26 4080,3401.06 v1(4080,3710)
INT5_N: U11.106 U29.20 | length 1355.7
  Top Layer w6: v1(3935,2805) 3940,2810 3940,3010 3997.72,3067.72 U11.106@3997.72,3165.63 ; U29.20@4565.98,2465 4565,2465.98 4565,2430 v1(4595,2400)
  MidLayer1 w6: v1(3935,2805) 4295,2805 4327.5,2772.5 4509.45,2590.55 4595,2505 v1(4595,2400)
INTERF_RES: U29.41 U44.1 U44.3 | length 3882.8
  Top Layer w6: U29.41@4405,2110 4480,2110 v1(4510,2080)
  Top Layer w8: U44.1@1484.96,1844.57 1480.39,1840 1425,1840 1405,1860 1405,1930 1419.57,1944.57 1539.57,1944.57 1570,1975 1570,2235 v2(1665,2330)
  MidLayer3 w6: v2(1665,2330) 1675,2340 2225,2340 2245,2320 2350,2320 2435,2405 2818,2405 2835,2388 4092,2388 4155,2325 v1(4195,2325)
  Bottom Layer w8: v1(4195,2325) 4245,2325 4490,2080 v1(4510,2080)
IR_REN_H_N: U16.51 U19.58 | length 1137.5
  Top Layer w6: U16.51@2003.94,3143 2003.94,3208.94 2022.72,3227.72 2105.2,3227.72 2208.48,3331 2575.21,3331 2626.21,3280 2855,3280 2883.47,3251.53 U19.58@2883.47,3143
IR_REN_L_N: U15.51 U18.58 | length 1086.8
  Top Layer w6: U15.51@1993.94,4093 1995,4091.94 1995,4185 2040,4230 2535,4230 2570,4195 2830,4195 2883.47,4141.53 U18.58@2883.47,4093
L_TCK: U10.12 U11.108 U23.12 | length 2615.7
  Top Layer w6: U11.108@4037.09,3165.63 4037.09,2962.91 v1(4055,2945)
  Top Layer w8: U10.12@3910,1880 3965,1880 v1(4000,1915) ; v2(5195,2930) 5205,2940 U23.12@5205,3005
  MidLayer3 w6: v1(4055,2945) 4060,2950 5175,2950 v2(5195,2930)
  Bottom Layer w6: v1(4000,1915) 4000,1944 3999,1945 3999,2784 4044,2829 4044,2934 v1(4055,2945)
L_TDI: U10.5 U11.110 U23.5 | length 2669.7
  Top Layer w6: v1(4070,2895) 4070,2900 4095,2925 4095,3010 4076.46,3028.54 U11.110@4076.46,3165.63
  Top Layer w8: v1(4025,2030) 4075,1980 U10.5@4135,1980 ; v2(5300,2860) 5305,2855 U23.5@5305,2785
  MidLayer3 w6: v1(4070,2895) 4111,2936 5124,2936 5160,2900 5260,2900 v2(5300,2860)
  Bottom Layer w6: v1(4025,2030) 4023,2030 4013,2040 4013,2778.2 4070,2835.2 v1(4070,2895)
L_TDO: U10.3 U11.111 U23.3 | length 2572.9
  Top Layer w6: U11.111@4096.14,3165.63 4096.14,3058.86 4125,3030 4125,2920 v1(4135,2910)
  Top Layer w8: v1(4050,1905) 4075,1880 U10.3@4130,1880 ; v2(5185,2860) 5205,2840 U23.3@5205,2785
  MidLayer3 w6: v1(4135,2910) 4170,2875 5170,2875 v2(5185,2860)
  Bottom Layer w6: v1(4050,1905) 4050,2045 4030,2065 4030,2240 4075,2285 4075,2800 4135,2860 v1(4135,2910)
L_TMS: U10.9 U11.109 U23.9 | length 2674.6
  Top Layer w6: U11.109@4056.77,3165.63 4056.77,2998.23 v1(4065,2990)
  Top Layer w8: U10.9@3910,2030 3950,2030 v1(3975,2055) ; U23.9@5355,3005 v2(5355,3095)
  MidLayer3 w6: v1(4065,2990) 4091,2964 5224,2964 v2(5355,3095)
  Bottom Layer w6: v1(3975,2055) 3975,2785 4027.24,2837.24 4030,2840 4030,2960 4060,2990 v1(4065,2990)
LED_1: J1.147 J2.147 R33.1 | length 3434.3
  Top Layer w6: v1(1290,925) 1302,913 1712,913 v1(1870,755) 1867,752 1867,546 1899.71,513.29 J1.147@1899.71,461.79
  Top Layer w8: v2(350,2725) R33.1@350,2820
  Bottom Layer w6: v2(350,2725) 370,2725 475,2620 475,1645 1215,905 1270,905 v1(1290,925) ; v1(1870,755) 1900,725 J2.147@1900,665 ; J2.147@1900.2,659.84 J2.147@1900.2,665
LED_2: J1.149 J2.149 R34.1 | length 3300.9
  Top Layer w6: v1(1230,935) 1268,897 1698,897 1835,760 1835,746 1853,728 1853,526 1875,504 J1.149@1875,470 ; J1.149@1874.71,461.79 J1.149@1874.71,470
  Top Layer w8: v2(465,2710) R34.1@465,2815
  Bottom Layer w6: v2(465,2710) 465,2705 505,2665 505,1660 v1(1230,935) ; v1(1835,755) 1875.2,714.8 J2.149@1875.2,659.84
LED_3: J1.148 J2.148 R35.1 | length 3302.2
  Top Layer w8: R35.1@580,2810 585,2810 585,2735 695,2625 695,2527.23 737.23,2485 737.23,2182.77 763.97,2156.03 800,2120 v2(1025,2120)
  Bottom Layer w6: v2(1025,2120) 1090,2120 1119.67,2090.33 1835,1375 1835,1035 1900.2,969.8 1900.2,860 1850.2,810 1745,810 1716,781 1716,649 1795,570 1829.71,570 1899.71,500 J1.148@1899.71,461.79
LED_4: J1.150 J2.150 R36.1 | length 4055.3
  Top Layer w8: R36.1@625,3500 v2(625,3565)
  Bottom Layer w6: v2(625,3565) 625,3515 945,3195 945,1685 1521.97,1108.03 1745,1108.03 1875,978.03 1875,914.76 J2.150@1875.2,914.96 1875.2,860 1841.2,826 1726,826 1700,800 1700,643.43 ; 1701,643.43 1701,629 1777.63,552.37 1822.33,552.37 1874.71,500 J1.150@1874.71,461.79
LED_5: J1.152 J2.152 R37.1 | length 4110.4
  Top Layer w8: R37.1@510,3500 v2(510,3565)
  Bottom Layer w6: v2(510,3565) 510,3535 892,3153 892,1693 1495,1090 1745,1090 1850.2,984.8 1850.2,860.2 1832.37,842.37 1712.37,842.37 1676,806 1676,629 1768.63,536.37 1813.33,536.37 1849.71,500 J1.152@1849.71,461.79
LED_6: J1.154 J2.154 R38.1 | length 4170.2
  Top Layer w8: R38.1@395,3500 v2(395,3570)
  Bottom Layer w6: v2(395,3570) 395,3510 446.52,3458.48 ; 435,3470 872,3033 872,1673 1470,1075 1740,1075 1825.2,989.8 J2.154@1825.2,914.96 ; J1.154@1824.71,461.79 1824.71,500 1804.33,520.37 1754.63,520.37 1660,615 1660,823.37 1695,858.37 1813.37,858.37 1825,870 1825,904.8 J2.154@1825.2,905
LED_S_1: U25.1 U29.13 | length 4868.8
  Top Layer w6: v1@4703.78,2401.22 U29.13@4703.78,2465
  Top Layer w8: U25.1@300,3050 300,3105 340,3145 v2(645,3145)
  MidLayer3 w6: v2(645,3145) 1060,2730 2415,2730 2451.59,2693.41 3121.39,2693.41 3128.82,2685.98 3213.8,2601 3785,2601 3809,2625 4465,2625 4690,2400 v1(4705,2400)
LED_S_2: D5.K U25.3 U29.14 | length 4937.9
  Top Layer w6: D5.K@4470,2800 4475,2795 4650,2795 4690,2755 4690,2605 4710,2585 4710,2550 4684.09,2524.09 U29.14@4684.09,2465 ; v1(4480,2730) D5.K@4480,2800
  Top Layer w8: U25.3@400,3050 400,3100 420,3120 v2(730,3120)
  MidLayer3 w6: v2(730,3120) 1100,2750 2585,2750 2629.59,2705.41 3510.41,2705.41 3535,2730 v1(4480,2730)
LED_S_3: U25.5 U29.5 | length 4897.1
  Top Layer w6: U29.5@4861.26,2465 4861.26,2348.74 v1(4865,2345)
  Top Layer w8: v2(500,2975) U25.5@500,3050
  MidLayer3 w6: v2(500,2975) 605,2975 896.7,2683.3 918.33,2661.67 1248.33,2661.67 1445,2465 2750,2465 2830,2545 4364.06,2545 4574.06,2335 4855,2335 v1(4865,2345)
LED_S_4: U25.9 U29.6 | length 4980.9
  Top Layer w6: v1(4835,2360) 4841.57,2366.57 U29.6@4841.57,2465
  Top Layer w8: v2(540,3185) 550,3195 U25.9@550,3270
  MidLayer3 w6: v2(540,3185) 540,3065 910.7,2694.3 921.88,2683.12 1263.88,2683.12 1470,2477 2737,2477 2819,2559 4367.03,2559 4577.03,2349 4824,2349 v1(4835,2360)
LED_S_5: U25.11 U29.7 | length 5037.2
  Top Layer w6: v1(4805,2375) 4821.89,2391.89 U29.7@4821.89,2475
  Top Layer w8: U25.11@450,3270 v2(450,3345)
  MidLayer3 w6: v2(450,3345) 460,3345 580,3225 580,3075 650.05,3004.95 950,2705 2370,2705 2424.6,2650.4 2674.19,2650.4 2751.6,2573 4370,2573 4580,2363 4794,2363 4805,2374 v1(4805,2375)
LED_S_6: U25.13 U29.8 | length 5141
  Top Layer w6: v1(4780,2390) 4802.2,2412.2 U29.8@4802.2,2465
  Top Layer w8: U25.13@350,3270 v2(350,3350)
  MidLayer3 w6: v2(350,3350) 350,3360 365,3375 485,3375 610,3250 610,3095 654.91,3050.09 987,2718 2397,2718 2433.59,2681.41 3113.59,2681.41 3208,2587 3792,2587 3816,2611 4459.2,2611 4693.2,2377 4769,2377 4780,2388 v1(4780,2390)
LOCK_EVENT: U9.C15 U11.76 | length 2544.6
  Top Layer w6: U9.C15@3181.18,1936.26 3161.5,1955.94 3161.5,2045 3192.5,2076 3351,2076 v1(3365,2090) ; U11.76@3874.45,3731.81 4108.19,3731.81 v1(4130,3710)
  MidLayer2 w6: v1(3365,2090) 3365,2289 3450,2374 3450,2654.8 3803.2,3008 3803.2,3107.29 4103,3407.09 4103,3690 4123,3710 v1(4130,3710)
M_ADDR0: U17.2 U17.5 U29.65 | length 4842
  Top Layer w6: v1(4715,2090) 4715,1995 4743.15,1966.85 U29.65@4743.15,1870.51
  Top Layer w8: U17.5@570,2500 510,2500 485,2475 485,2380 515,2350 U17.2@570,2350 645,2350 v2(655,2340)
  MidLayer3 w6: v2(655,2340) 660,2340 710,2290 2380,2290 2464.89,2374.89 2790.11,2374.89 2815,2350 3617,2350 3628.34,2338.66 3640,2327 3902.4,2327 4100,2129.4 4675.6,2129.4 v1(4715,2090)
M_ADDR1: U17.9 U29.66 | length 4866.4
  Top Layer w6: v1(4740,2065) 4762.83,2042.17 U29.66@4762.83,1870.51
  Top Layer w8: U17.9@350,2550 v2(435,2550)
  MidLayer3 w6: v2(435,2550) 435,2524 685,2274 2456,2274 2485,2245 3559.03,2245 3627.03,2313 3899.43,2313 4097.43,2115 4650,2115 4700,2065 v1(4740,2065)
M_ADDR2: U17.12 U29.67 | length 5007.1
  Top Layer w6: U29.67@4780,1870 4780,2040 v1(4790,2050)
  Top Layer w8: v2(265,2400) U17.12@350,2400 U17.12@355,2400
  MidLayer3 w6: v2(265,2400) 535,2400 675,2260 2453.03,2260 2480.03,2233 3564,2233 3630,2299 3893.63,2299 4152.63,2040 4770,2040 4780,2050 v1(4790,2050)
M_SEL_N: R31.1 U11.113 U23.1 U23.4 U23.10 U23.13 | length 2063.6
  Top Layer w6: U11.113@4135.51,3165.63 4135.51,3084.89 4165,3055.4 v1(4165,2990)
  Top Layer w10: v2(5005,3070) 5140,3070 5155,3055 U23.13@5155,3000
  Top Layer w15: U23.1@5105,2785 5105,2870 5155,2920 U23.13@5155,3000 ; 5134.46,2899.46 5289.46,2899.46 ; R31.1@5254.99,2645 5255,2865 5305,2915 U23.10@5305,3015
  MidLayer3 w6: v1(4165,2990) 4177,2978 4913,2978 v2(5005,3070)
MI_DAT0: U9.J2 U29.25 | length 2840.9
  Top Layer w6: v3(2649.68,1680.35) U9.J2@2669.37,1700.04 ; v1(4450,2535) 4467.56,2517.44 U29.25@4467.56,2465
  MidLayer1 w6: v1(2610,2505) 2693,2505 2721,2533 3227.4,2533 3255.4,2561 4399,2561 4425,2535 v1(4450,2535)
  MidLayer2 w6: v1(2610,2505) 2625,2490 2625,2320 2600,2295 2600,2096.91 2637.68,2059.23 2637.68,1692.35 v3(2649.68,1680.35)
MI_DAT1: U9.J1 U29.26 | length 2655.8
  Top Layer w6: v3(2610.32,1680.35) U9.J1@2630,1700.04 ; v1(4390,2450) 4405,2435 U29.26@4405,2405
  MidLayer1 w6: v1(2605,2346) 2609.3,2346 2645.76,2382.46 2790,2382.46 2813.46,2359 3257.63,2359 3343.63,2445 3915,2445 3960,2490 4350,2490 v1(4390,2450)
  MidLayer2 w6: v1@2603,2348 2587,2332 2587,2092.94 2625,2054.94 2625,1695.04 v3(2610.32,1680.35)
MI_DAT2: U9.K6 U29.27 | length 2256.1
  Top Layer w6: v3(2807.17,1680.35) U9.K6@2826.85,1660.67 ; v1(4335,2460) 4335.31,2459.69 4335.31,2399.69 4350.71,2384.29 U29.27@4406.54,2384.29
  MidLayer2 w6: v1(3400,1700) 3435,1735 3435,2080 3860,2505 4290,2505 v1(4335,2460)
  MidLayer3 w6: v3(2807.17,1680.35) 2826.85,1700.04 3335,1700.04 3335.04,1700 v1(3400,1700)
MI_DAT3: U9.L6 U29.28 | length 2294.6
  Top Layer w6: U9.L6@2826.85,1621.3 v3(2846.54,1640.98) ; v1(4300,2460) 4300,2405 4322.12,2382.88 4340,2365 U29.28@4410,2365
  MidLayer2 w6: v1(3485,1700) 3485,1705 3455,1735 3455,2083.03 3862.97,2491 4269,2491 v1(4300,2460)
  MidLayer3 w6: v3(2846.54,1640.98) 2866.22,1660.67 3445.67,1660.67 v1(3485,1700)
MI_DAT4: U9.L3 U29.29 | length 3159.5
  Top Layer w6: v3(2689.06,1640.98) U9.L3@2708.74,1621.3
  Top Layer w8: U29.29@4406.54,2344.92 4455,2344.92 4475,2364.92 v1(4475,2375)
  MidLayer1 w6: v1(2565,2500) 2582.81,2482.19 2692.19,2482.19 2725,2515 3230,2515 3264,2549 4391,2549 4458.59,2481.41 4475,2465 v1(4475,2375)
  MidLayer2 w6: v1(2565,2500) 2575,2490 2575,2087.97 2613,2049.97 2613,1723 2590.67,1700.67 2590.67,1660.63 2610.32,1640.98 v3(2689.06,1640.98)
MI_DAT5: U9.K1 U29.30 | length 2609
  Top Layer w6: v1@2511.81,1678.19 2529.33,1660.67 U9.K1@2630,1660.67 ; v1(4295,2350) 4345,2350 4369.76,2325.24 U29.30@4406.54,2325.24
  MidLayer1 w6: v1(2675,2275) 2681,2269 3218.55,2269 3351.55,2402 4239,2402 4291,2350 v1(4295,2350)
  Bottom Layer w6: v1(2513.63,1680) 2515,1680 2515,1685 2575,1745 2575,2175 v1(2675,2275)
MI_DAT6: U9.L2 U29.31 | length 2768.9
  Top Layer w6: v1(2580,1640.98) 2649.68,1640.98 U9.L2@2669.37,1621.3 ; v1(4335,2320) 4350,2305 4405.98,2305 U29.31@4406.54,2305.55
  MidLayer1 w6: v1(2555,2305) 2619.8,2305 2663.23,2348.43 2673.26,2358.46 2770,2358.46 2793.46,2335 3267.58,2335 3348.58,2416 4259,2416 4335,2340 v1(4335,2320)
  MidLayer2 w6: v1(2555,2305) 2555,2091 2601,2045 2601,1727.97 2575,1701.97 2575,1645 2579.02,1640.98 v1(2580,1640.98)
MI_DAT7: U9.L1 U29.32 | length 3066.6
  Top Layer w6: v1@2545,1604.23 2562.06,1621.3 2569.51,1621.3 U9.L1@2630,1621.3 ; U29.32@4407.4,2285 U29.32@4406.54,2285.87 4479.13,2285.87 v1(4495,2270)
  MidLayer1 w6: v1(2510,2325) 2620,2325 2665.46,2370.46 2779.54,2370.46 2803,2347 3262.61,2347 3345.61,2430 3515.61,2430 4290,2430 4450,2270 v1(4495,2270)
  MidLayer2 w6: v1(2510,2325) 2510,2099 2577,2032 2577,1737.91 2545.63,1706.54 2545.63,1602.56 v1(2545,1601.93)
MO_DAT0: U9.K2 U29.43 | length 2452.6
  Top Layer w6: U9.K2@2669.37,1660.67 v3(2689.06,1680.35) ; v1(4340,2080) 4350,2070 U29.43@4405,2070
  MidLayer1 w6: v1(2635,2145) 2639,2145 2714.94,2220.94 3377.91,2220.94 3466.97,2310 4105,2310 4335,2080 v1(4340,2080)
  MidLayer2 w6: v1(2635,2145) 2649.68,2130.32 2649.68,1719.72 v3(2689.06,1680.35)
MO_DAT1: U9.N2 U29.44 | length 2673.9
  Top Layer w6: v1(2545,1415) 2545,1500 2607.24,1562.24 2649.68,1562.24 U9.N2@2669.37,1542.56 ; v1(4270,1745) 4248,1767 4248,1940.83 4356.82,2049.65 U29.44@4406.54,2049.65
  MidLayer3 w6: v1(2545,1415) 2641,1319 3574,1319 3665,1410 4073.03,1410 4270,1606.97 v1(4270,1745)
MO_DAT2: U9.N1 U29.45 | length 2132.3
  Top Layer w6: U9.N1@2630,1542.56 v3(2649.68,1522.87) ; v1(4290,1775) 4260,1805 4260,1930.3 4359.66,2029.96 U29.45@4406.54,2029.96
  Bottom Layer w6: v3(2649.68,1522.87) 2728.43,1522.87 2748.11,1542.56 3180,1542.56 3302.44,1665 4140,1665 4255,1780 4285,1780 v1(4290,1775)
MO_DAT3: U9.K5 U29.46 | length 2055.9
  Top Layer w6: v3(2767.8,1680.35) U9.K5@2787.48,1660.67 ; v1(4320,1790) 4275.01,1834.99 4275.01,1925.51 4359.77,2010.28 U29.46@4406.54,2010.28
  MidLayer1 w6: v3(2767.8,1680.35) 2787.48,1660.67 2866.22,1660.67 2905.59,1621.3 3327.3,1621.3 3364.21,1658.21 3633.21,1658.21 3690,1715 v1(3690,1710)
  MidLayer2 w6: v1(3690,1710) 3730,1670 4235,1670 4320,1755 v1(4320,1790)
MO_DAT4: U9.L4 U29.47 | length 1927.5
  Top Layer w6: U9.L4@2748.11,1621.3 v3(2767.8,1601.61) ; v1(4300,1855) 4300,1930.7 4359.3,1990 U29.47@4415,1990
  MidLayer1 w6: v3(2767.8,1601.61) 2787.48,1581.93 3070.26,1581.93 3092.33,1604 3334.2,1604 3374.41,1644.21 3655,1644.21 3715,1704.21 3715,1745 3735,1765 3950,1765 v1(3985,1800)
  MidLayer3 w6: v1(3985,1800) 4055,1800 4115,1860 4300,1860 v1(4300,1855)
MO_DAT5: U9.R1 U29.48 | length 2321.4
  Top Layer w6: v3(2610.32,1444.13) U9.R1@2630,1463.82 ; v1(4355,1820) 4351.93,1820 4336.93,1835 4336.93,1947.84 4360,1970.91 U29.48@4406.54,1970.91
  MidLayer3 w6: v3(2610.32,1444.13) 2630,1424.45 3335.55,1424.45 3400,1360 3590,1360 3665,1435 4080,1435 4169.39,1524.39 4245,1600 4245,1771.03 4284.97,1811 4341,1811 4355,1825 v1(4355,1820)
MO_DAT6: U9.P2 U29.49 | length 2239.7
  Top Layer w6: v3(2649.68,1483.5) U9.P2@2669.37,1503.19 ; v1(4375,1845) 4375,1846.46 4351.46,1870 4351.46,1941.46 4361.22,1951.22 U29.49@4406.54,1951.22
  MidLayer3 w6: v3(2649.68,1483.5) 2669.37,1463.82 3323.82,1463.82 3365,1505 3605,1505 3660,1450 4075,1450 4162.37,1537.37 4205.12,1580.12 4220,1595 4220,1775 4268,1823 4323,1823 4350,1850 4370,1850 v1(4375,1845)
MO_DAT7: U9.P1 U29.50 | length 2220.1
  Top Layer w6: v3(2610.32,1483.5) U9.P1@2630,1503.19 ; v1(4405,1855) 4406.54,1856.54 U29.50@4406.54,1931.54
  MidLayer3 w6: v3(2610.32,1483.5) 2630,1503.19 3318.98,1503.19 3335.79,1520 3620,1520 3675,1465 4073.03,1465 4198.03,1590 4198.03,1778.03 4255,1835 4315,1835 4348,1868 4392,1868 v1(4405,1855)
